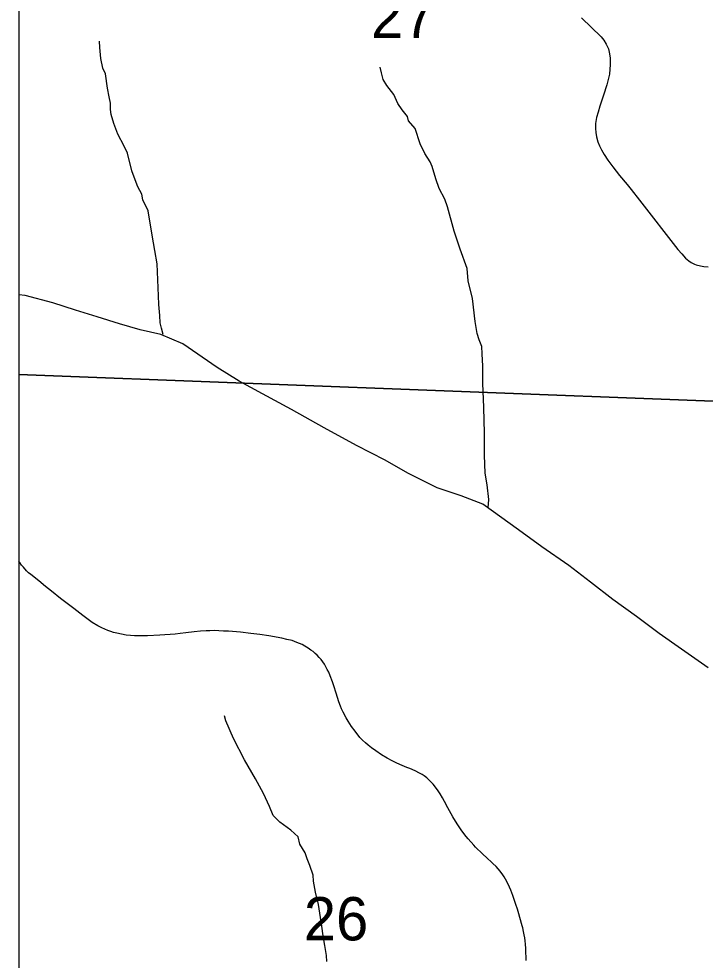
# Model space of a CAD drawing. Extents: x 6.3 to 40.3, y 9 to 31.
# Drawn here: x 8.445 to 9.108, y 26.729 to 27.639 of the extents above; entities that cross this region are included whole.
import ezdxf

# ---------------------------------------------------------------- set-up
doc = ezdxf.new("R2010")
doc.units = 0
for name, color, linetype in [('Default', 7, 'Continuous'), ('GM_X_Corporation', 7, 'Continuous'), ('GM_X_County_Road', 7, 'Continuous'), ('GM_X_Minor_River', 7, 'Continuous'), ('GM_X_Section_Text', 7, 'Continuous'), ('GM_X_Township_Road', 7, 'Continuous'), ('SH_Cut_Line', 7, 'Continuous'), ('SH_Data', 7, 'Continuous')]:
    doc.layers.add(name, color=color, linetype=linetype)

msp = doc.modelspace()

# ---------------------------------------------------------------- linework, layer by layer
at = {"layer": 'Default'}
for points in [[(12.96715, 29.14265), (12.49185, 29.15927), (11.62211, 29.19333), (10.61758, 29.225), (10.04965, 29.2462), (9.83607, 29.25073), (8.86731, 29.28288), (8.4446, 29.29582), (8.4446, 23.14572)], [(12.5872, 27.77659), (11.71746, 27.81064), (10.71294, 27.84232), (10.145, 27.86352), (9.93143, 27.86805), (8.96266, 27.9002), (8.4446, 27.91606), (8.4446, 23.14572)]]:
    msp.add_lwpolyline(points, dxfattribs=at)
at = {"layer": 'GM_X_Corporation'}
for points in [[(8.4446, 28.28644), (8.4446, 27.29578), (9.31753, 27.26201), (9.3471, 28.26219)], [(8.4446, 27.29578), (8.4446, 26.2901), (9.29206, 26.26681), (9.31753, 27.26201)]]:
    msp.add_lwpolyline(points, close=True, dxfattribs=at)
at = {"layer": 'GM_X_County_Road'}
msp.add_lwpolyline([(8.93518, 26.72894), (8.93509, 26.73202), (8.9349, 26.73699), (8.93475, 26.74061), (8.93442, 26.74489), (8.93408, 26.74809), (8.93371, 26.751), (8.93326, 26.75401), (8.93257, 26.75706), (8.9318, 26.76068), (8.93137, 26.76248), (8.92904, 26.77073), (8.92797, 26.77422), (8.92663, 26.77881), (8.9253, 26.78307), (8.92222, 26.79203), (8.92016, 26.79722), (8.91767, 26.80285), (8.91514, 26.80775), (8.91378, 26.80999), (8.91249, 26.81186), (8.90998, 26.81533), (8.9081, 26.8178), (8.90605, 26.82001), (8.90295, 26.82294), (8.90157, 26.82419), (8.89748, 26.82798), (8.89292, 26.83223), (8.88626, 26.8388), (8.88453, 26.8406), (8.87914, 26.84662), (8.87715, 26.84901), (8.87295, 26.85445), (8.86838, 26.86118), (8.86416, 26.86812), (8.85929, 26.87681), (8.85609, 26.88279), (8.85434, 26.88619), (8.852, 26.89032), (8.85015, 26.89301), (8.84848, 26.89529), (8.84506, 26.89959), (8.84179, 26.90316), (8.83914, 26.90563), (8.83667, 26.90756), (8.83473, 26.90879), (8.83213, 26.91033), (8.82776, 26.91247), (8.82268, 26.91465), (8.81983, 26.91581), (8.81525, 26.91766), (8.81016, 26.91997), (8.80567, 26.92213), (8.80071, 26.92478), (8.79535, 26.92798), (8.78965, 26.93182), (8.78556, 26.93472), (8.78234, 26.93715), (8.77965, 26.9394), (8.77683, 26.94209), (8.77438, 26.9448), (8.76972, 26.9507), (8.76638, 26.95525), (8.76299, 26.96052), (8.76114, 26.96378), (8.75805, 26.96923), (8.75661, 26.97233), (8.75553, 26.97497), (8.75395, 26.97906), (8.75134, 26.98742), (8.74914, 26.99452), (8.74773, 26.99859), (8.74566, 27.00435), (8.74419, 27.00777), (8.74288, 27.01048), (8.74156, 27.01303), (8.74008, 27.0155), (8.73852, 27.01779), (8.73696, 27.01993), (8.73507, 27.02207), (8.73309, 27.02413), (8.73112, 27.02601), (8.72907, 27.02774), (8.7271, 27.02922), (8.72434, 27.03108), (8.72126, 27.03307), (8.71847, 27.03448), (8.71356, 27.0366), (8.71115, 27.03752), (8.70877, 27.03834), (8.70375, 27.03958), (8.69882, 27.04065), (8.68632, 27.04287), (8.6776, 27.0442), (8.66906, 27.04525), (8.65887, 27.0464), (8.64749, 27.04737), (8.64265, 27.04762), (8.63783, 27.04788), (8.63363, 27.04804), (8.62936, 27.04796), (8.62567, 27.04783), (8.62022, 27.04739), (8.6141, 27.04677), (8.60613, 27.0458), (8.60062, 27.04509), (8.5957, 27.04459), (8.58088, 27.04356), (8.56915, 27.04301), (8.56367, 27.04285), (8.55641, 27.04301), (8.55258, 27.0432), (8.54847, 27.04361), (8.54395, 27.04443), (8.53943, 27.04541), (8.53622, 27.04623), (8.5335, 27.04705), (8.53055, 27.04817), (8.52477, 27.05055), (8.5211, 27.05249), (8.51557, 27.05587), (8.50655, 27.06253), (8.49781, 27.06942), (8.49136, 27.07426), (8.48496, 27.07911), (8.47623, 27.08601), (8.47048, 27.09066), (8.46392, 27.0962), (8.45619, 27.10225), (8.45394, 27.10402), (8.45196, 27.10593), (8.44902, 27.10921), (8.44728, 27.11142), (8.44562, 27.11373), (8.4446, 27.11527)], dxfattribs=at)
at = {"layer": 'GM_X_Minor_River'}
for points in [[(8.58427, 27.3344), (8.58252, 27.3405), (8.58133, 27.34542), (8.58087, 27.35264), (8.58, 27.36326), (8.57953, 27.37161), (8.57844, 27.40274), (8.57603, 27.41563), (8.57359, 27.43042), (8.56955, 27.45393), (8.5645, 27.46451), (8.56368, 27.46982), (8.55981, 27.47699), (8.55708, 27.4838), (8.55395, 27.4925), (8.54959, 27.50955), (8.54648, 27.51635), (8.54028, 27.52806), (8.53638, 27.53828), (8.53401, 27.54699), (8.5332, 27.55192), (8.53313, 27.55799), (8.53193, 27.56406), (8.53032, 27.5724), (8.52827, 27.58643), (8.52594, 27.59172), (8.52394, 27.6012), (8.52307, 27.61182), (8.52263, 27.6179)], [(8.89842, 27.16668), (8.89908, 27.17489), (8.89741, 27.18892), (8.89539, 27.20029), (8.89482, 27.21776), (8.89498, 27.23903), (8.89434, 27.26371), (8.89333, 27.28724), (8.89315, 27.30357), (8.89264, 27.31572), (8.89219, 27.32255), (8.88984, 27.32898), (8.88788, 27.33542), (8.88586, 27.34679), (8.88334, 27.36917), (8.87899, 27.38622), (8.8781, 27.39798), (8.87145, 27.4169), (8.86556, 27.43431), (8.85924, 27.45779), (8.85651, 27.46498), (8.85108, 27.47556), (8.84795, 27.48464), (8.8444, 27.49675), (8.84245, 27.50129), (8.83705, 27.50921), (8.83277, 27.51866), (8.82768, 27.53342), (8.82153, 27.54095), (8.82034, 27.54512), (8.81534, 27.55152), (8.8111, 27.55755), (8.80721, 27.56625), (8.80028, 27.57491), (8.7968, 27.58095), (8.79522, 27.58739), (8.79402, 27.5927)], [(9.11106, 27.01198), (9.08531, 27.0301), (9.06374, 27.04519), (9.04178, 27.0618), (9.01906, 27.07803), (8.99749, 27.09501), (8.97629, 27.11087), (8.95017, 27.12898), (8.92783, 27.14559), (8.89338, 27.17013), (8.87218, 27.17843), (8.84909, 27.18598), (8.8207, 27.20032), (8.79874, 27.21278), (8.77111, 27.22712), (8.73969, 27.2441), (8.70827, 27.26184), (8.68025, 27.27694), (8.65754, 27.28902), (8.63634, 27.30223), (8.60303, 27.32526), (8.58183, 27.33432), (8.56177, 27.33885), (8.54208, 27.34451), (8.5205, 27.3513), (8.49931, 27.35772), (8.47735, 27.36489), (8.45085, 27.37206), (8.4446, 27.37258)], [(8.74246, 26.72815), (8.74202, 26.73384), (8.7404, 26.7437), (8.73878, 26.75279), (8.73754, 26.76228), (8.73428, 26.78312), (8.73149, 26.79524), (8.72948, 26.80586), (8.72904, 26.81155), (8.7259, 26.82101), (8.72355, 26.82744), (8.72159, 26.83311), (8.71619, 26.84141), (8.71459, 26.8486), (8.70769, 26.85499), (8.69697, 26.86285), (8.69045, 26.86923), (8.68694, 26.87793), (8.68111, 26.8904), (8.67336, 26.90474), (8.66291, 26.92324), (8.65206, 26.94363), (8.64466, 26.96064), (8.64347, 26.96556)]]:
    msp.add_lwpolyline(points, dxfattribs=at)
at = {"layer": 'GM_X_Township_Road'}
msp.add_lwpolyline([(8.98865, 27.64046), (9.00762, 27.62222), (9.01019, 27.61871), (9.01244, 27.61499), (9.01461, 27.61052), (9.01577, 27.60578), (9.01643, 27.60151), (9.01643, 27.59543), (9.0156, 27.58606), (9.01314, 27.5757), (9.01, 27.56579), (9.00648, 27.55507), (9.0046, 27.54933), (9.00315, 27.54394), (9.00229, 27.53842), (9.00215, 27.53345), (9.00243, 27.52974), (9.00315, 27.52545), (9.00447, 27.52066), (9.00601, 27.51659), (9.00799, 27.51273), (9.01044, 27.50843), (9.01414, 27.50272), (9.01887, 27.49626), (9.02545, 27.48812), (9.03273, 27.47935), (9.03671, 27.47455), (9.04471, 27.46423), (9.08186, 27.41639), (9.08563, 27.4123), (9.08918, 27.40808), (9.09256, 27.40538), (9.09461, 27.40401), (9.09789, 27.40226), (9.0996, 27.40166), (9.10374, 27.40055), (9.10679, 27.40007), (9.11112, 27.3997)], dxfattribs=at)
at = {"layer": 'SH_Cut_Line'}
msp.add_lwpolyline([(12.96715, 29.14265), (12.49185, 29.15927), (11.62211, 29.19333), (10.61758, 29.225), (10.04965, 29.2462), (9.83607, 29.25073), (8.86731, 29.28288), (8.4446, 29.29582), (8.4446, 23.14572)], dxfattribs=at)
at = {"layer": 'SH_Data'}
msp.add_line((8.4446, 29.94572), (8.4446, 23.14572), dxfattribs=at)

# ---------------------------------------------------------------- texts
at = {"layer": 'GM_X_Section_Text'}
for s, p in [('27', (8.7852, 27.621)), ('26', (8.7202, 26.7485))]:
    msp.add_text(s, height=0.041856, rotation=0.00001, dxfattribs=at).set_placement(p)

doc.saveas('drawing.dxf')
